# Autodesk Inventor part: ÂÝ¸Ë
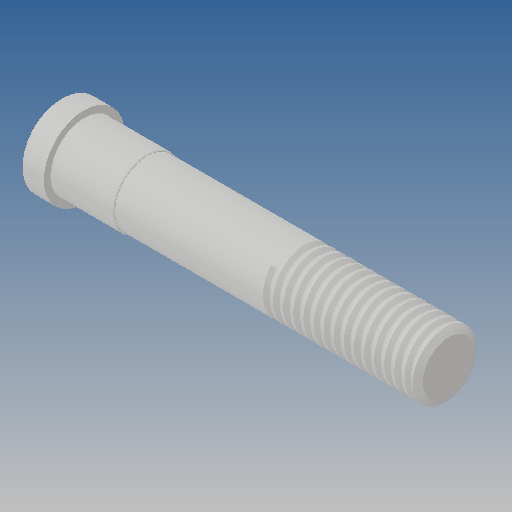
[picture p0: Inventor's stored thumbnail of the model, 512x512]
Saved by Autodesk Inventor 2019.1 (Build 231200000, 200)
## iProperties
Created: 2012-10
Part Number: ÂÝ¸Ë
Material: Ogólny
Document SubType Name: Modeling
Designer: CADENGINEERING4
Density: 1 g/cm^3
Appearance: Domyślna
Author: CADENGINEERING4
Revision Number: ÈÎºÎ
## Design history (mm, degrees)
feature "ÇÐ³ý-É¨Ãè1"
node "Bryła1"
